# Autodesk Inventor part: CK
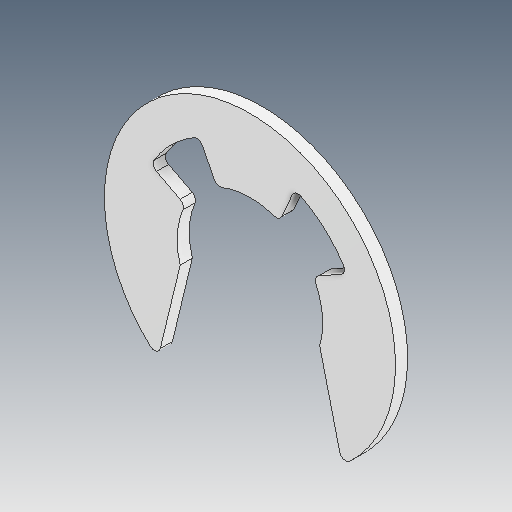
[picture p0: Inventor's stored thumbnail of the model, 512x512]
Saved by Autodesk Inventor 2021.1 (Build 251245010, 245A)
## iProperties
Created: 2021-05
Part Number: CK
Material: Ogólny
Document SubType Name: Modeling
Designer: user
Density: 1 g/cm^3
Appearance: Domyślna
Author: user
Revision Number: ÈÎºÎ
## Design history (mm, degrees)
feature "ÊäÈë1"
node "Bryła1"
